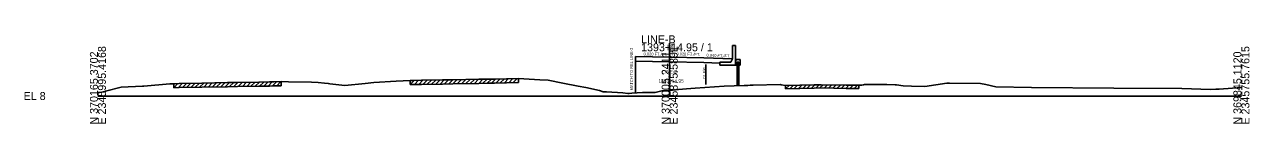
# Model space of a CAD drawing. Extents: x -26 to 2400, y -10 to 9525.
# Drawn here: x -25.7 to 402.8, y 1490.3 to 1521.3 of the extents above; entities that cross this region are included whole.
import ezdxf

# ---------------------------------------------------------------- set-up
doc = ezdxf.new("R2010")
doc.units = 0
for name, color, linetype in [('RD_GPK_XS_Cell', 7, 'Continuous'), ('RD_XS_Base', 7, 'Continuous'), ('RD_XS_ExGround', 7, 'Continuous'), ('RD_XS_ExPaveRet', 7, 'Continuous'), ('RD_XS_ExRW', 7, 'Continuous'), ('RD_XS_MatchLine', 7, 'Continuous'), ('RD_XS_MedBWall', 7, 'Continuous'), ('RD_XS_Pave', 7, 'Continuous'), ('RD_XS_PaveShd', 7, 'Continuous'), ('RD_XS_TX_Elev_EX', 7, 'Continuous'), ('RD_XS_TX_Elev_PR', 7, 'Continuous'), ('RD_XS_TX_Slope', 7, 'Continuous'), ('RD_XS_TX_Station', 7, 'Continuous')]:
    doc.layers.add(name, color=color, linetype=linetype)

msp = doc.modelspace()

# ---------------------------------------------------------------- linework, layer by layer
at = {"layer": 'RD_GPK_XS_Cell'}
for p, q in [((200, 1500), (200, 1518.47)), ((0, 1500), (200, 1500)), ((200, 1500), (400, 1500))]:
    msp.add_line(p, q, dxfattribs=at)
at = {"layer": 'RD_XS_Base'}
for p, q in [((188, 1512.26), (199.97, 1512.02)), ((199.94, 1512.02), (211.95, 1511.78)), ((211.95, 1511.78), (217.58, 1511.56))]:
    msp.add_line(p, q, dxfattribs=at)
at = {"layer": 'RD_XS_ExGround'}
msp.add_lwpolyline([(0, 1501.21), (0.6, 1501.29), (2.05, 1501.5), (2.7, 1501.67), (8.14, 1503.05), (15.59, 1503.48), (16.08, 1503.5), (25.17, 1504.22), (26.53, 1504.32), (28.36, 1504.36), (36.35, 1504.55), (45.28, 1504.71), (48.81, 1504.77), (56.23, 1504.88), (60.06, 1504.94), (61.58, 1504.97), (64.15, 1505.03), (66.63, 1504.97), (74.73, 1504.86), (77.03, 1504.71), (79.31, 1504.55), (80.56, 1504.42), (81.1, 1504.32), (86.35, 1503.73), (93.48, 1504.38), (96.55, 1504.74), (104.32, 1505.2), (109.2, 1505.47), (110.52, 1505.48), (113.14, 1505.51), (120.5, 1505.64), (124.15, 1505.7), (133.28, 1505.87), (136.56, 1505.93), (138.72, 1505.96), (147.08, 1506.16), (154.57, 1505.72), (157.47, 1505.51), (162.57, 1504.53), (167.94, 1503.47), (170.63, 1502.93), (175.5, 1501.89), (176.71, 1501.51), (177.87, 1501.51), (183.64, 1501.06), (185.33, 1500.87), (185.83, 1500.86), (186.73, 1501), (190.5, 1501.24), (194.88, 1501.21), (197.3, 1501.81), (199.31, 1501.86), (200, 1501.94), (203.07, 1502.32), (205.87, 1502.5), (208.96, 1502.78), (219.02, 1503.51), (226.01, 1503.73), (227.33, 1503.74), (228.2, 1503.78), (229.23, 1503.8), (238.67, 1504.04), (239.05, 1503.96), (240.58, 1503.65), (250.51, 1503.9), (253.01, 1503.96), (261.73, 1503.83), (266.15, 1503.76), (266.52, 1503.78), (267.25, 1503.83), (267.77, 1503.95), (268.14, 1504.03), (272.3, 1504.01), (273.58, 1504.01), (275.97, 1503.99), (278.88, 1503.96), (279.34, 1503.88), (281.66, 1503.58), (284.61, 1503.45), (289.3, 1503.33), (296.99, 1504.5), (297.33, 1504.54), (297.85, 1504.53), (308.75, 1504.34), (310.58, 1504.01), (314.15, 1503.26), (326.58, 1502.98), (355.37, 1502.8), (379.19, 1502.58), (389.17, 1502.3), (391.02, 1502.38), (392.22, 1502.41), (396.91, 1502.77), (400, 1503.02)], dxfattribs=at)
at = {"layer": 'RD_XS_ExPaveRet'}
for p, q in [((26.53, 1502.89), (28, 1504.36)), ((26.53, 1502.89), (26.53, 1504.32)), ((28.03, 1502.92), (29.5, 1504.39)), ((29.53, 1502.96), (31, 1504.43)), ((31.03, 1502.99), (32.5, 1504.46)), ((32.53, 1503.03), (34, 1504.5)), ((34.03, 1503.06), (35.5, 1504.53)), ((35.53, 1503.1), (37, 1504.56)), ((37.03, 1503.13), (38.49, 1504.59)), ((38.53, 1503.15), (39.99, 1504.62)), ((40.03, 1503.18), (41.49, 1504.64)), ((41.53, 1503.21), (42.99, 1504.67)), ((43.03, 1503.23), (44.49, 1504.69)), ((44.53, 1503.26), (45.99, 1504.72)), ((46.03, 1503.28), (47.49, 1504.74)), ((47.53, 1503.31), (48.99, 1504.77)), ((49.03, 1503.33), (50.49, 1504.79)), ((50.53, 1503.35), (51.99, 1504.81)), ((52.03, 1503.38), (53.49, 1504.84)), ((53.53, 1503.4), (54.99, 1504.86)), ((55.03, 1503.42), (56.49, 1504.88)), ((56.53, 1503.45), (57.99, 1504.91)), ((58.03, 1503.47), (59.49, 1504.93)), ((59.53, 1503.49), (61, 1504.96)), ((61.03, 1503.52), (62.5, 1504.99)), ((62.53, 1503.56), (64, 1505.03)), ((64.15, 1505.03), (64.15, 1503.59)), ((109.2, 1504.03), (110.65, 1505.48)), ((109.2, 1504.03), (109.2, 1505.47)), ((110.7, 1504.05), (112.15, 1505.5)), ((112.2, 1504.06), (113.66, 1505.52)), ((113.14, 1504.07), (120.5, 1504.21)), ((113.7, 1504.08), (115.17, 1505.55)), ((115.2, 1504.11), (116.67, 1505.57)), ((116.7, 1504.14), (118.17, 1505.6)), ((118.2, 1504.16), (119.67, 1505.63)), ((119.7, 1504.19), (121.17, 1505.65)), ((120.5, 1504.21), (124.15, 1504.27)), ((121.2, 1504.22), (122.66, 1505.68)), ((122.7, 1504.24), (124.16, 1505.7)), ((124.15, 1504.27), (133.28, 1504.43)), ((124.2, 1504.27), (125.67, 1505.73)), ((125.7, 1504.3), (127.17, 1505.76)), ((127.2, 1504.32), (128.67, 1505.79)), ((128.7, 1504.35), (130.17, 1505.81)), ((130.2, 1504.38), (131.67, 1505.84)), ((131.7, 1504.41), (133.17, 1505.87)), ((133.2, 1504.43), (134.67, 1505.9)), ((133.28, 1504.43), (136.56, 1504.5)), ((134.7, 1504.46), (136.17, 1505.92)), ((136.2, 1504.49), (137.66, 1505.95)), ((136.56, 1504.5), (138.72, 1504.52)), ((137.7, 1504.51), (139.16, 1505.97)), ((138.72, 1504.52), (147.08, 1504.72)), ((139.2, 1504.54), (140.67, 1506.01)), ((140.7, 1504.57), (142.17, 1506.04)), ((142.2, 1504.61), (143.67, 1506.08)), ((143.7, 1504.64), (145.17, 1506.11)), ((145.2, 1504.68), (146.67, 1506.15)), ((147.08, 1506.16), (147.08, 1504.72)), ((26.53, 1502.89), (28.36, 1502.93)), ((28.36, 1502.93), (36.35, 1503.12)), ((36.35, 1503.12), (45.28, 1503.27)), ((45.28, 1503.27), (48.81, 1503.33)), ((48.81, 1503.33), (56.23, 1503.44)), ((56.23, 1503.44), (60.06, 1503.5)), ((60.06, 1503.5), (61.58, 1503.54)), ((61.58, 1503.54), (64.15, 1503.59)), ((109.2, 1504.03), (110.52, 1504.05)), ((110.52, 1504.05), (113.14, 1504.07)), ((240.58, 1502.51), (241.75, 1503.68)), ((240.58, 1502.51), (240.58, 1503.65)), ((240.58, 1502.51), (250.51, 1502.76)), ((242.08, 1502.55), (243.25, 1503.72)), ((243.58, 1502.59), (244.75, 1503.76)), ((245.08, 1502.62), (246.25, 1503.8)), ((246.58, 1502.66), (247.75, 1503.83)), ((248.08, 1502.7), (249.25, 1503.87)), ((249.58, 1502.74), (250.75, 1503.91)), ((250.51, 1502.76), (253.01, 1502.82)), ((251.08, 1502.77), (252.25, 1503.94)), ((252.58, 1502.81), (253.72, 1503.95)), ((253.01, 1502.82), (261.73, 1502.69)), ((254.08, 1502.8), (255.21, 1503.93)), ((255.58, 1502.78), (256.71, 1503.91)), ((257.08, 1502.76), (258.21, 1503.89)), ((258.58, 1502.74), (259.71, 1503.86)), ((260.08, 1502.71), (261.21, 1503.84)), ((261.58, 1502.69), (262.71, 1503.82)), ((261.73, 1502.69), (266.15, 1502.62)), ((263.08, 1502.67), (264.21, 1503.79)), ((264.58, 1502.64), (265.71, 1503.77)), ((266.15, 1503.76), (266.15, 1502.62))]:
    msp.add_line(p, q, dxfattribs=at)
at = {"layer": 'RD_XS_ExRW'}
msp.add_line((212.64, 1504.05), (212.64, 1511.05), dxfattribs=at)
at = {"layer": 'RD_XS_MatchLine'}
msp.add_line((188, 1513.9), (188, 1501.08), dxfattribs=at)
at = {"layer": 'RD_XS_MedBWall'}
for p, q in [((222, 1513.02), (222, 1517.69)), ((222, 1517.69), (223, 1517.69)), ((222, 1513.02), (222, 1517.69)), ((222, 1517.69), (223, 1517.69)), ((223, 1517.69), (223, 1513.02)), ((221.37, 1511.85), (221.86, 1512.85)), ((221.86, 1512.85), (222, 1513.02)), ((223, 1513.02), (223.08, 1513.02)), ((223.08, 1513.02), (223.08, 1510.85)), ((223.08, 1512.85), (223.15, 1512.85)), ((223.15, 1512.85), (224.65, 1512.85)), ((223.15, 1510.85), (223.15, 1512.85)), ((224.65, 1512.85), (224.65, 1510.85)), ((217.58, 1510.85), (217.58, 1511.85)), ((217.58, 1511.85), (221.37, 1511.85)), ((223.08, 1510.85), (217.58, 1510.85)), ((223.65, 1510.85), (223.15, 1510.85)), ((224.15, 1511.85), (223.65, 1511.85)), ((223.65, 1511.85), (223.65, 1510.85)), ((223.65, 1510.85), (223.65, 1503.66)), ((224.15, 1510.85), (224.15, 1511.85)), ((224.65, 1510.85), (224.15, 1510.85)), ((224.15, 1510.85), (224.15, 1503.67))]:
    msp.add_line(p, q, dxfattribs=at)
at = {"layer": 'RD_XS_Pave'}
for p, q in [((188, 1513.9), (200, 1513.66)), ((200, 1513.66), (212, 1513.42))]:
    msp.add_line(p, q, dxfattribs=at)
at = {"layer": 'RD_XS_PaveShd'}
msp.add_line((212, 1513.42), (222, 1513.02), dxfattribs=at)

# ---------------------------------------------------------------- texts
at = {"layer": 'RD_GPK_XS_Cell'}
for s, p in [('E 2345995.4168', (2.8, 1490)), ('E 2345875.5891', (202.8, 1490)), ('E 2345755.7615', (402.8, 1490)), ('N 370165.3702', (0, 1490)), ('N 370005.2411', (200, 1490)), ('N 369845.1120', (400, 1490))]:
    msp.add_text(s, height=2.8, rotation=90, dxfattribs=at).set_placement(p)
for s, p in [('1393+14.95 / 1', (190, 1515.67)), ('LINE-B', (190, 1518.47)), ('EL 8', (-26, 1498.6))]:
    msp.add_text(s, height=2.8, dxfattribs=at).set_placement(p)
at = {"layer": 'RD_XS_ExRW'}
msp.add_text('EX. R/W ', height=0.75, rotation=90, dxfattribs=at).set_placement((212.39, 1506.08))
at = {"layer": 'RD_XS_TX_Elev_EX'}
msp.add_text('9.94', height=1, rotation=90, dxfattribs=at).set_placement((200.5, 1501.94))
at = {"layer": 'RD_XS_TX_Elev_PR'}
msp.add_text(' 21.66', height=1.2, rotation=90, dxfattribs=at).set_placement((201.2, 1513.66))
at = {"layer": 'RD_XS_TX_Slope'}
for s, rotation, p in [('0.020 FT./FT.', 358.8542, (190.88, 1514.24)), ('0.020 FT./FT.', 358.8542, (202.36, 1514.24)), ('0.040 FT./FT.', 357.7094, (212.88, 1513.83))]:
    msp.add_text(s, height=1, rotation=rotation, dxfattribs=at).set_placement(p)
at = {"layer": 'RD_XS_TX_Station'}
msp.add_text('MATCH TO REL LINE-3', height=1, rotation=90, dxfattribs=at).set_placement((187.17, 1501.95))
for s, p in [('LINE-B', (197.43, 1507.96)), ('1393+14.95', (196.1, 1504.66))]:
    msp.add_text(s, height=1.2, dxfattribs=at).set_placement(p)

doc.saveas('drawing.dxf')
